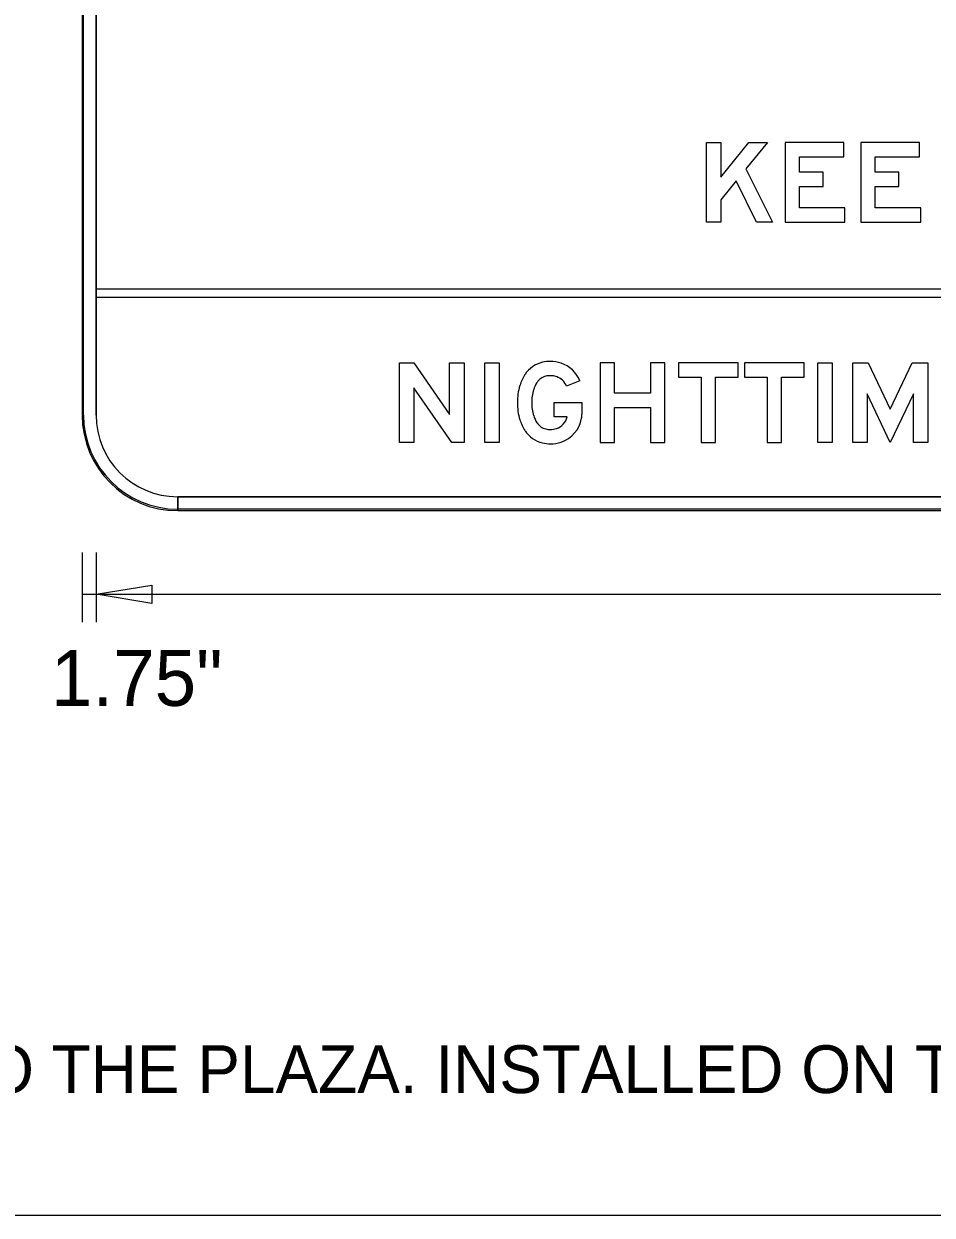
# Model space of a CAD drawing. Extents: x 17890071 to 17890754, y 17897628 to 17897992.
# Drawn here: x 17890113.83 to 17890123.33, y 17897797.14 to 17897809.61 of the extents above; entities that cross this region are included whole.
import ezdxf

# ---------------------------------------------------------------- set-up
doc = ezdxf.new("R2010")
doc.units = 0
for name, color, linetype in [('GSBWFill', 7, 'Continuous'), ('GSColorFill', 7, 'Continuous'), ('GSDims', 7, 'Continuous'), ('GSOutline', 7, 'Continuous'), ('SheetLinesMisc2_dp', 7, 'Continuous')]:
    doc.layers.add(name, color=color, linetype=linetype)

msp = doc.modelspace()

# ---------------------------------------------------------------- linework, layer by layer
at = {"layer": 'GSBWFill'}
for p, q in [((17890114.439, 17897813.514), (17890114.439, 17897805.514)), ((17890114.585, 17897805.514), (17890114.585, 17897813.514)), ((17890134.253, 17897806.832), (17890114.587, 17897806.832)), ((17890114.587, 17897806.832), (17890114.587, 17897806.749)), ((17890114.587, 17897806.749), (17890134.253, 17897806.749)), ((17890115.439, 17897804.514), (17890115.439, 17897804.66)), ((17890133.439, 17897804.66), (17890115.441, 17897804.66)), ((17890115.441, 17897804.66), (17890115.441, 17897804.514)), ((17890115.441, 17897804.514), (17890133.439, 17897804.514))]:
    msp.add_line(p, q, dxfattribs=at)
for points in [[(17890121.607, 17897808.366), (17890121.383, 17897808.091), (17890121.661, 17897807.532), (17890121.493, 17897807.532), (17890121.279, 17897807.963), (17890121.119, 17897807.766), (17890121.119, 17897807.532), (17890120.969, 17897807.532), (17890120.969, 17897808.366), (17890121.119, 17897808.366), (17890121.119, 17897808.003), (17890121.413, 17897808.366)], [(17890122.419, 17897807.682), (17890121.944, 17897807.682), (17890121.944, 17897807.906), (17890122.19, 17897807.906), (17890122.19, 17897808.056), (17890121.944, 17897808.056), (17890121.944, 17897808.216), (17890122.407, 17897808.216), (17890122.407, 17897808.366), (17890121.794, 17897808.366), (17890121.794, 17897807.532), (17890122.419, 17897807.532)], [(17890123.211, 17897807.682), (17890122.736, 17897807.682), (17890122.736, 17897807.906), (17890122.982, 17897807.906), (17890122.982, 17897808.056), (17890122.736, 17897808.056), (17890122.736, 17897808.216), (17890123.198, 17897808.216), (17890123.198, 17897808.366), (17890122.586, 17897808.366), (17890122.586, 17897807.532), (17890123.211, 17897807.532)], [(17890118.434, 17897806.061), (17890118.434, 17897805.228), (17890118.305, 17897805.228), (17890117.909, 17897805.799), (17890117.909, 17897805.228), (17890117.759, 17897805.228), (17890117.759, 17897806.061), (17890117.91, 17897806.061), (17890118.284, 17897805.521), (17890118.284, 17897806.061)], [(17890118.651, 17897805.228), (17890118.651, 17897806.061), (17890118.801, 17897806.061), (17890118.801, 17897805.228)], [(17890120.384, 17897805.744), (17890120.009, 17897805.744), (17890120.009, 17897806.061), (17890119.859, 17897806.061), (17890119.859, 17897805.228), (17890120.009, 17897805.228), (17890120.009, 17897805.594), (17890120.384, 17897805.594), (17890120.384, 17897805.228), (17890120.534, 17897805.228), (17890120.534, 17897806.061), (17890120.384, 17897806.061)], [(17890120.676, 17897805.911), (17890120.913, 17897805.911), (17890120.913, 17897805.228), (17890121.063, 17897805.228), (17890121.063, 17897805.911), (17890121.301, 17897805.911), (17890121.301, 17897806.061), (17890120.676, 17897806.061)], [(17890121.368, 17897805.911), (17890121.605, 17897805.911), (17890121.605, 17897805.228), (17890121.755, 17897805.228), (17890121.755, 17897805.911), (17890121.993, 17897805.911), (17890121.993, 17897806.061), (17890121.368, 17897806.061)], [(17890122.134, 17897805.228), (17890122.134, 17897806.061), (17890122.284, 17897806.061), (17890122.284, 17897805.228)], [(17890122.893, 17897805.577), (17890123.123, 17897806.061), (17890123.284, 17897806.061), (17890123.284, 17897805.228), (17890123.134, 17897805.228), (17890123.134, 17897805.736), (17890122.893, 17897805.228), (17890122.651, 17897805.736), (17890122.651, 17897805.228), (17890122.501, 17897805.228), (17890122.501, 17897806.061), (17890122.662, 17897806.061)]]:
    msp.add_lwpolyline(points, close=True, dxfattribs=at)
for points in [[(17890119.645, 17897805.872), (17890119.506, 17897805.816)], [(17890119.513, 17897805.494), (17890119.376, 17897805.494), (17890119.376, 17897805.644), (17890119.668, 17897805.644), (17890119.668, 17897805.525)]]:
    msp.add_lwpolyline(points, dxfattribs=at)
for centre, radius, start, end in [((17890119.337, 17897805.714), 0.362, 90, 103.1315), ((17890119.337, 17897805.726), 0.35, 71.2015, 90), ((17890119.323, 17897805.774), 0.3, 103.1315, 146.7742), ((17890119.345, 17897805.751), 0.324, 22.0367, 71.2015), ((17890119.435, 17897805.7), 0.434, 146.7742, 163.4624), ((17890119.435, 17897805.7), 0.284, 146.7742, 163.4624), ((17890119.323, 17897805.774), 0.15, 103.1315, 146.7742), ((17890119.337, 17897805.714), 0.212, 90, 103.1315), ((17890119.337, 17897805.726), 0.2, 71.2015, 90), ((17890119.345, 17897805.751), 0.174, 22.0367, 71.2015), ((17890119.623, 17897805.644), 0.631, 163.4624, 180), ((17890119.623, 17897805.644), 0.481, 163.4624, 180), ((17890119.623, 17897805.644), 0.631, 180, 196.5376), ((17890119.623, 17897805.644), 0.481, 180, 196.5376), ((17890115.439, 17897805.514), 1, 180, 270), ((17890115.439, 17897805.514), 0.854, 180, 270), ((17890119.435, 17897805.589), 0.434, 196.5376, 213.2258), ((17890119.435, 17897805.589), 0.284, 196.5376, 213.2258), ((17890119.345, 17897805.538), 0.174, 288.7985, 345.418), ((17890119.345, 17897805.538), 0.324, 288.7985, 349.6765), ((17890119.42, 17897805.525), 0.247, 349.6765, 0), ((17890119.323, 17897805.515), 0.3, 213.2258, 256.8685), ((17890119.323, 17897805.515), 0.15, 213.2258, 256.8685), ((17890119.337, 17897805.575), 0.212, 256.8685, 270), ((17890119.337, 17897805.563), 0.2, 270, 288.7985), ((17890119.337, 17897805.575), 0.362, 256.8685, 270), ((17890119.337, 17897805.563), 0.35, 270, 288.7985)]:
    msp.add_arc(centre, radius, start, end, dxfattribs=at)
at = {"layer": 'GSColorFill'}
for p, q in [((17890114.439, 17897813.514), (17890114.439, 17897805.514)), ((17890114.439, 17897813.514), (17890114.439, 17897805.514)), ((17890114.439, 17897813.514), (17890114.439, 17897805.514)), ((17890114.454, 17897805.514), (17890114.454, 17897813.514)), ((17890114.585, 17897805.514), (17890114.585, 17897813.514)), ((17890134.253, 17897806.832), (17890114.587, 17897806.832)), ((17890114.587, 17897806.832), (17890114.587, 17897806.749)), ((17890114.587, 17897806.749), (17890134.253, 17897806.749)), ((17890115.439, 17897804.514), (17890115.439, 17897804.66)), ((17890133.439, 17897804.66), (17890115.441, 17897804.66)), ((17890115.441, 17897804.66), (17890115.441, 17897804.514)), ((17890115.439, 17897804.514), (17890115.439, 17897804.529)), ((17890133.439, 17897804.529), (17890115.439, 17897804.529)), ((17890115.439, 17897804.529), (17890115.439, 17897804.514)), ((17890115.439, 17897804.514), (17890133.439, 17897804.514)), ((17890115.439, 17897804.514), (17890133.439, 17897804.514)), ((17890115.441, 17897804.514), (17890133.439, 17897804.514))]:
    msp.add_line(p, q, dxfattribs=at)
for points in [[(17890121.607, 17897808.366), (17890121.383, 17897808.091), (17890121.661, 17897807.532), (17890121.493, 17897807.532), (17890121.279, 17897807.963), (17890121.119, 17897807.766), (17890121.119, 17897807.532), (17890120.969, 17897807.532), (17890120.969, 17897808.366), (17890121.119, 17897808.366), (17890121.119, 17897808.003), (17890121.413, 17897808.366)], [(17890122.419, 17897807.682), (17890121.944, 17897807.682), (17890121.944, 17897807.906), (17890122.19, 17897807.906), (17890122.19, 17897808.056), (17890121.944, 17897808.056), (17890121.944, 17897808.216), (17890122.407, 17897808.216), (17890122.407, 17897808.366), (17890121.794, 17897808.366), (17890121.794, 17897807.532), (17890122.419, 17897807.532)], [(17890123.211, 17897807.682), (17890122.736, 17897807.682), (17890122.736, 17897807.906), (17890122.982, 17897807.906), (17890122.982, 17897808.056), (17890122.736, 17897808.056), (17890122.736, 17897808.216), (17890123.198, 17897808.216), (17890123.198, 17897808.366), (17890122.586, 17897808.366), (17890122.586, 17897807.532), (17890123.211, 17897807.532)], [(17890118.434, 17897806.061), (17890118.434, 17897805.228), (17890118.305, 17897805.228), (17890117.909, 17897805.799), (17890117.909, 17897805.228), (17890117.759, 17897805.228), (17890117.759, 17897806.061), (17890117.91, 17897806.061), (17890118.284, 17897805.521), (17890118.284, 17897806.061)], [(17890118.651, 17897805.228), (17890118.651, 17897806.061), (17890118.801, 17897806.061), (17890118.801, 17897805.228)], [(17890120.384, 17897805.744), (17890120.009, 17897805.744), (17890120.009, 17897806.061), (17890119.859, 17897806.061), (17890119.859, 17897805.228), (17890120.009, 17897805.228), (17890120.009, 17897805.594), (17890120.384, 17897805.594), (17890120.384, 17897805.228), (17890120.534, 17897805.228), (17890120.534, 17897806.061), (17890120.384, 17897806.061)], [(17890120.676, 17897805.911), (17890120.913, 17897805.911), (17890120.913, 17897805.228), (17890121.063, 17897805.228), (17890121.063, 17897805.911), (17890121.301, 17897805.911), (17890121.301, 17897806.061), (17890120.676, 17897806.061)], [(17890121.368, 17897805.911), (17890121.605, 17897805.911), (17890121.605, 17897805.228), (17890121.755, 17897805.228), (17890121.755, 17897805.911), (17890121.993, 17897805.911), (17890121.993, 17897806.061), (17890121.368, 17897806.061)], [(17890122.134, 17897805.228), (17890122.134, 17897806.061), (17890122.284, 17897806.061), (17890122.284, 17897805.228)], [(17890122.893, 17897805.577), (17890123.123, 17897806.061), (17890123.284, 17897806.061), (17890123.284, 17897805.228), (17890123.134, 17897805.228), (17890123.134, 17897805.736), (17890122.893, 17897805.228), (17890122.651, 17897805.736), (17890122.651, 17897805.228), (17890122.501, 17897805.228), (17890122.501, 17897806.061), (17890122.662, 17897806.061)]]:
    msp.add_lwpolyline(points, close=True, dxfattribs=at)
for points in [[(17890119.645, 17897805.872), (17890119.506, 17897805.816)], [(17890119.513, 17897805.494), (17890119.376, 17897805.494), (17890119.376, 17897805.644), (17890119.668, 17897805.644), (17890119.668, 17897805.525)]]:
    msp.add_lwpolyline(points, dxfattribs=at)
for centre, radius, start, end in [((17890119.337, 17897805.714), 0.362, 90, 103.1315), ((17890119.337, 17897805.726), 0.35, 71.2015, 90), ((17890119.323, 17897805.774), 0.3, 103.1315, 146.7742), ((17890119.345, 17897805.751), 0.324, 22.0367, 71.2015), ((17890119.435, 17897805.7), 0.434, 146.7742, 163.4624), ((17890119.435, 17897805.7), 0.284, 146.7742, 163.4624), ((17890119.323, 17897805.774), 0.15, 103.1315, 146.7742), ((17890119.337, 17897805.714), 0.212, 90, 103.1315), ((17890119.337, 17897805.726), 0.2, 71.2015, 90), ((17890119.345, 17897805.751), 0.174, 22.0367, 71.2015), ((17890119.623, 17897805.644), 0.631, 163.4624, 180), ((17890119.623, 17897805.644), 0.481, 163.4624, 180), ((17890119.623, 17897805.644), 0.631, 180, 196.5376), ((17890119.623, 17897805.644), 0.481, 180, 196.5376), ((17890115.439, 17897805.514), 1, 180, 270), ((17890115.439, 17897805.514), 1, 180, 270), ((17890115.439, 17897805.514), 1, 180, 270), ((17890115.439, 17897805.514), 0.985, 180, 270), ((17890115.439, 17897805.514), 0.854, 180, 270), ((17890119.435, 17897805.589), 0.434, 196.5376, 213.2258), ((17890119.435, 17897805.589), 0.284, 196.5376, 213.2258), ((17890119.345, 17897805.538), 0.174, 288.7985, 345.418), ((17890119.345, 17897805.538), 0.324, 288.7985, 349.6765), ((17890119.42, 17897805.525), 0.247, 349.6765, 0), ((17890119.323, 17897805.515), 0.3, 213.2258, 256.8685), ((17890119.323, 17897805.515), 0.15, 213.2258, 256.8685), ((17890119.337, 17897805.575), 0.212, 256.8685, 270), ((17890119.337, 17897805.563), 0.2, 270, 288.7985), ((17890119.337, 17897805.575), 0.362, 256.8685, 270), ((17890119.337, 17897805.563), 0.35, 270, 288.7985)]:
    msp.add_arc(centre, radius, start, end, dxfattribs=at)
at = {"layer": 'GSDims'}
for p, q in [((17890114.439, 17897804.077), (17890114.439, 17897803.347)), ((17890114.585, 17897804.077), (17890114.585, 17897803.347)), ((17890114.439, 17897803.639), (17890114.585, 17897803.639)), ((17890114.585, 17897803.639), (17890134.273, 17897803.639))]:
    msp.add_line(p, q, dxfattribs=at)
msp.add_lwpolyline([(17890114.585, 17897803.639), (17890115.168, 17897803.736), (17890115.168, 17897803.542)], close=True, dxfattribs=at)
at = {"layer": 'GSOutline'}
for p, q in [((17890114.439, 17897813.514), (17890114.439, 17897805.514)), ((17890114.585, 17897813.514), (17890114.585, 17897805.514)), ((17890134.253, 17897806.832), (17890114.587, 17897806.832)), ((17890114.587, 17897806.832), (17890114.587, 17897806.749)), ((17890114.587, 17897806.749), (17890134.253, 17897806.749)), ((17890115.439, 17897804.66), (17890133.439, 17897804.66)), ((17890115.439, 17897804.514), (17890133.439, 17897804.514))]:
    msp.add_line(p, q, dxfattribs=at)
for points in [[(17890121.607, 17897808.366), (17890121.383, 17897808.091), (17890121.661, 17897807.532), (17890121.493, 17897807.532), (17890121.279, 17897807.963), (17890121.119, 17897807.766), (17890121.119, 17897807.532), (17890120.969, 17897807.532), (17890120.969, 17897808.366), (17890121.119, 17897808.366), (17890121.119, 17897808.003), (17890121.413, 17897808.366)], [(17890122.419, 17897807.682), (17890121.944, 17897807.682), (17890121.944, 17897807.906), (17890122.19, 17897807.906), (17890122.19, 17897808.056), (17890121.944, 17897808.056), (17890121.944, 17897808.216), (17890122.407, 17897808.216), (17890122.407, 17897808.366), (17890121.794, 17897808.366), (17890121.794, 17897807.532), (17890122.419, 17897807.532)], [(17890123.211, 17897807.682), (17890122.736, 17897807.682), (17890122.736, 17897807.906), (17890122.982, 17897807.906), (17890122.982, 17897808.056), (17890122.736, 17897808.056), (17890122.736, 17897808.216), (17890123.198, 17897808.216), (17890123.198, 17897808.366), (17890122.586, 17897808.366), (17890122.586, 17897807.532), (17890123.211, 17897807.532)], [(17890118.434, 17897806.061), (17890118.434, 17897805.228), (17890118.305, 17897805.228), (17890117.909, 17897805.799), (17890117.909, 17897805.228), (17890117.759, 17897805.228), (17890117.759, 17897806.061), (17890117.91, 17897806.061), (17890118.284, 17897805.521), (17890118.284, 17897806.061)], [(17890118.651, 17897805.228), (17890118.651, 17897806.061), (17890118.801, 17897806.061), (17890118.801, 17897805.228)], [(17890120.384, 17897805.744), (17890120.009, 17897805.744), (17890120.009, 17897806.061), (17890119.859, 17897806.061), (17890119.859, 17897805.228), (17890120.009, 17897805.228), (17890120.009, 17897805.594), (17890120.384, 17897805.594), (17890120.384, 17897805.228), (17890120.534, 17897805.228), (17890120.534, 17897806.061), (17890120.384, 17897806.061)], [(17890120.676, 17897805.911), (17890120.913, 17897805.911), (17890120.913, 17897805.228), (17890121.063, 17897805.228), (17890121.063, 17897805.911), (17890121.301, 17897805.911), (17890121.301, 17897806.061), (17890120.676, 17897806.061)], [(17890121.368, 17897805.911), (17890121.605, 17897805.911), (17890121.605, 17897805.228), (17890121.755, 17897805.228), (17890121.755, 17897805.911), (17890121.993, 17897805.911), (17890121.993, 17897806.061), (17890121.368, 17897806.061)], [(17890122.134, 17897805.228), (17890122.134, 17897806.061), (17890122.284, 17897806.061), (17890122.284, 17897805.228)], [(17890122.893, 17897805.577), (17890123.123, 17897806.061), (17890123.284, 17897806.061), (17890123.284, 17897805.228), (17890123.134, 17897805.228), (17890123.134, 17897805.736), (17890122.893, 17897805.228), (17890122.651, 17897805.736), (17890122.651, 17897805.228), (17890122.501, 17897805.228), (17890122.501, 17897806.061), (17890122.662, 17897806.061)]]:
    msp.add_lwpolyline(points, close=True, dxfattribs=at)
for points in [[(17890119.645, 17897805.872), (17890119.506, 17897805.816)], [(17890119.513, 17897805.494), (17890119.376, 17897805.494), (17890119.376, 17897805.644), (17890119.668, 17897805.644), (17890119.668, 17897805.525)]]:
    msp.add_lwpolyline(points, dxfattribs=at)
for centre, radius, start, end in [((17890119.337, 17897805.714), 0.362, 90, 103.1315), ((17890119.337, 17897805.726), 0.35, 71.2015, 90), ((17890119.323, 17897805.774), 0.3, 103.1315, 146.7742), ((17890119.345, 17897805.751), 0.324, 22.0367, 71.2015), ((17890119.435, 17897805.7), 0.434, 146.7742, 163.4624), ((17890119.435, 17897805.7), 0.284, 146.7742, 163.4624), ((17890119.323, 17897805.774), 0.15, 103.1315, 146.7742), ((17890119.337, 17897805.714), 0.212, 90, 103.1315), ((17890119.337, 17897805.726), 0.2, 71.2015, 90), ((17890119.345, 17897805.751), 0.174, 22.0367, 71.2015), ((17890119.623, 17897805.644), 0.631, 163.4624, 180), ((17890119.623, 17897805.644), 0.481, 163.4624, 180), ((17890119.623, 17897805.644), 0.631, 180, 196.5376), ((17890119.623, 17897805.644), 0.481, 180, 196.5376), ((17890115.439, 17897805.514), 1, 180, 270), ((17890115.439, 17897805.514), 0.854, 180, 270), ((17890119.435, 17897805.589), 0.434, 196.5376, 213.2258), ((17890119.435, 17897805.589), 0.284, 196.5376, 213.2258), ((17890119.345, 17897805.538), 0.174, 288.7985, 345.418), ((17890119.345, 17897805.538), 0.324, 288.7985, 349.6765), ((17890119.42, 17897805.525), 0.247, 349.6765, 0), ((17890119.323, 17897805.515), 0.3, 213.2258, 256.8685), ((17890119.323, 17897805.515), 0.15, 213.2258, 256.8685), ((17890119.337, 17897805.575), 0.212, 256.8685, 270), ((17890119.337, 17897805.563), 0.2, 270, 288.7985), ((17890119.337, 17897805.575), 0.362, 256.8685, 270), ((17890119.337, 17897805.563), 0.35, 270, 288.7985)]:
    msp.add_arc(centre, radius, start, end, dxfattribs=at)
at = {"layer": 'SheetLinesMisc2_dp'}
msp.add_line((17890100.188, 17897797.144), (17890151.359, 17897797.144), dxfattribs=at)

# ---------------------------------------------------------------- texts
at = {"layer": 'GSDims'}
for s, height, p in [('1.75"', 0.5833, (17890114.114, 17897802.472)), ('TYPICAL: FINAL SIGN BEFORE ENTRY TO THE PLAZA. INSTALLED ON THE LEFT IN THE MEDIAN', 0.5, (17890100.561, 17897798.421))]:
    msp.add_text(s, height=height, dxfattribs=at).set_placement(p)

doc.saveas('drawing.dxf')
